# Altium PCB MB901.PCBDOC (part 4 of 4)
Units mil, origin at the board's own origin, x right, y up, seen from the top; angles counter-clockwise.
Board outline 4505 x 7005 mil, 4 copper layers (TopLayer, GND, VCC, BottomLayer); 333 components, 312 nets, 1570 pads, 794 vias.
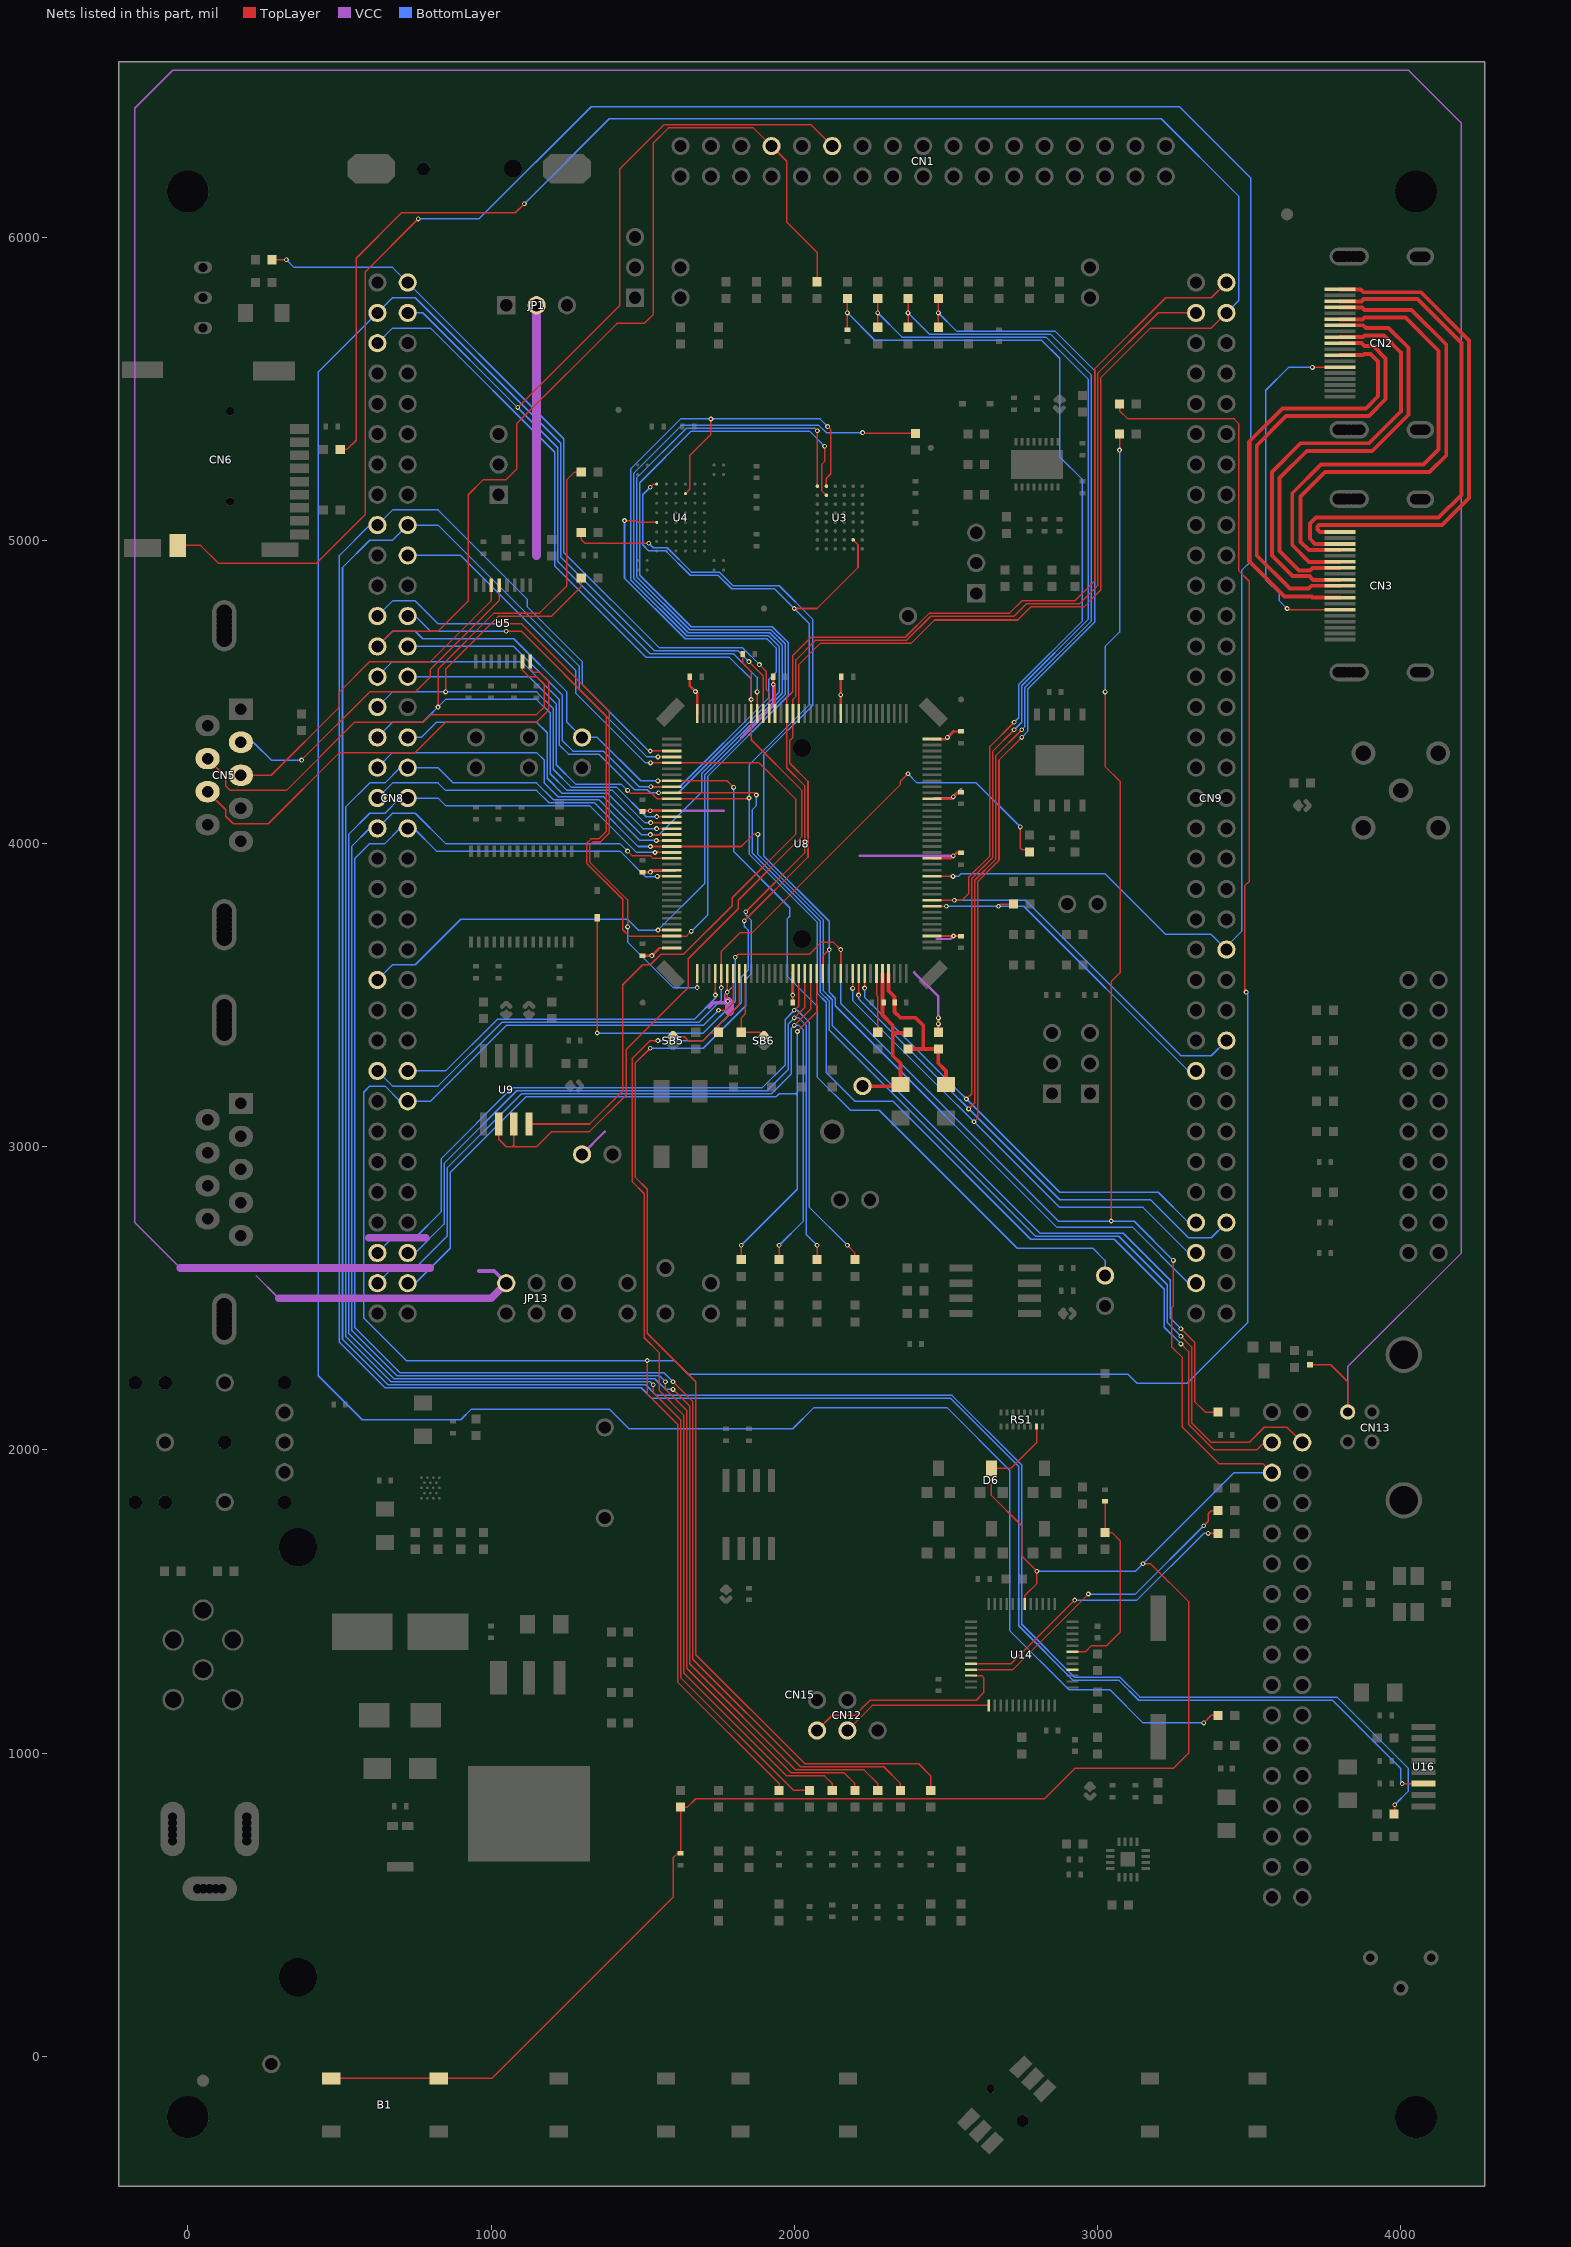
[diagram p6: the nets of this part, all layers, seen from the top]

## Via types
v1: diameter 16, hole 8, TopLayer to BottomLayer, tented both sides, 671 vias
v2: diameter 16, hole 8, TopLayer to BottomLayer, 117 vias
v3: diameter 50, hole 28, TopLayer to BottomLayer, 5 vias
v4: diameter 50, hole 28, TopLayer to BottomLayer, tented both sides, 1 vias

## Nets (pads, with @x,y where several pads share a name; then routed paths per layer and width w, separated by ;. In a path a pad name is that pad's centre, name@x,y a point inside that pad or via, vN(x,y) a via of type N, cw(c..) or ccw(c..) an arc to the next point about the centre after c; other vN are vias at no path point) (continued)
PC1: C10.2 CN9.65 R6.1 U8.27 | length 4896.7
  TopLayer w5: v1(2192.32,3522.32) U8.27@2192.32,3570.87 ; C10.2@2475,5702.5 R6.1@2475,5797.5 ; v1(2592.63,3082.37) 2605,3094.74 2605,3875 2675,3945 2675,4275 v1(2750,4350)
  BottomLayer w5: v1(2192.32,3522.32) 2192.32,3482.68 2875,2800 3150,2800 3300,2650 CN9.65@3325,2650 ; v1(2475,5750) 2535,5690 2860,5690 2990,5560 2990,4730 2770.59,4510.59 2770.59,4370.59 v1(2750,4350)
PC2: C9.2 CN9.64 R5.1 U8.28 | length 5015.9
  TopLayer w5: v1(2212.01,3500) U8.28@2212.01,3570.87 ; C9.2@2375,5702.5 R5.1@2375,5797.5 ; v1(2575,3125) 2595,3145 2595,3879.14 2665,3949.14 2665,4290 v1(2750,4375)
  BottomLayer w5: v1(2212.01,3500) 2212.01,3487.99 2875,2825 3175,2825 3300,2700 3375,2700 CN9.64@3425,2750 ; v1(2375,5750) 2445,5680 2845,5680 2980,5545 2980,4734.14 2760,4514.14 2760,4430 ; v1(2750,4375) 2760.59,4385.59 2760.59,4430
PC3: C8.2 CN9.63 R4.1 U8.29 | length 4899.1
  TopLayer w5: v1(2231.69,3523.31) U8.29@2231.69,3570.87 ; C8.2@2275,5702.5 R4.1@2275,5797.5 ; v1(2567.58,3157.42) 2585,3174.84 2585,3885 2655,3955 2655,4305 v1(2725,4375)
  BottomLayer w5: v1(2231.69,3523.31) 2231.69,3493.31 2875,2850 3200,2850 3300,2750 CN9.63@3325,2750 ; v1(2275,5750) 2355,5670 2830,5670 2970,5530 2970,4740 2750,4520 2750,4400 v1(2725,4375)
PC4: CN9.53 R47.1 U8.44 | length 1147.9
  TopLayer w5: U8.44@2454.13,3793.31 v1(2501.69,3793.31) ; v1(2673.31,3793.31) 2680,3800 R47.1@2722.5,3800
  BottomLayer w5: v1(2501.69,3793.31) 2756.69,3793.31 3300,3250 CN9.53@3325,3250
PC5: C7.2 CN9.52 R3.2 U8.45 | length 4076.7
  TopLayer w5: C7.2@2175,5694.5 R3.2@2175,5797.5 ; U8.45@2454.13,3812.99 2552.99,3812.99 2575,3835 2575,3889.14 2645,3959.14 2645,4320 v1(2725,4400)
  BottomLayer w5: v1(2175,5750) 2265,5660 2815,5660 2875,5600 2875,5275 2950,5200 2950,4734.14 2740,4524.14 2740,4415 v1(2725,4400) ; v1(2527.99,3812.99) 2762.01,3812.99 3275,3300 3375,3300 CN9.52@3425,3350
PC6: CN8.2 R1.1 U8.96 | length 2554.2
  TopLayer w5: R1.1@277.5,5925 v2(325,5925) ; v1(1885,4590) 1907.05,4567.95 1907.05,4507.95 1916.73,4498.27 U8.96@1916.73,4429.13
  BottomLayer w5: v2(325,5925) 350,5900 675,5900 1240,5335 1240,4960 1555,4645 1830,4645 v1(1885,4590)
PC7: CN8.3 R95.1 U8.97 | length 9587.2
  TopLayer w5: v1(1850,4600) 1897.05,4552.95 U8.97@1897.05,4429.13 ; v2(3350,1100) 3375,1125 R95.1@3397.5,1125
  BottomLayer w5: v1(1850,4600) 1815,4635 1540,4635 1230,4945 1230,5320 750,5800 675,5800 430,5555 430,2245 575,2100 900,2100 935,2135 1390,2135 1455,2070 1995,2070 2065,2140 2503.43,2140 2710,1933.43 2710,1405 2905,1210 3040,1210 3150,1100 v2(3350,1100)
PC8: CN1.23 CN8.4 U8.98 | length 3703.3
  TopLayer w5: v2(1088.08,5438.08) 1425,5775 1425,6225 1570,6370 2055,6370 CN1.23@2125,6300 ; U8.98@1877.36,4429.13 v1(1877.36,4500)
  BottomLayer w5: CN8.4@725,5750 775,5750 v2@1087.5,5437.5 ; v2@1088.08,5436.92 1220,5305 1220,4930 1525,4625 1800,4625 1877.36,4547.64 v1(1877.36,4500)
PC9: CN8.5 R40.2 U8.99 U9.2 U9.3 | length 4435.7
  TopLayer w5: U9.2@1025,3075 1025,3025 1050,3000 1150,3000 1200,3050 1325,3050 1445,3170 1445,3320 1650,3525 1650,3620 1815,3785 1815,3812.57 2025.11,4022.68 2025.11,4174.89 1857.68,4342.32 1857.68,4567.32 1830.5,4594.5 R40.2@1830.5,4625 ; 1070,3000 1075,3005 1080,3000 ; 1075,3000 U9.3@1075,3075
  BottomLayer w5: CN8.5@625,5650 675,5700 800,5700 1210,5290 1210,4915 1510,4615 1785,4615 1857.68,4542.32 v1(1857.68,4475)
PC10: CN8.17 U8.111 U16.3 | length 8663.8
  TopLayer w5: v1(1525,4305) 1525.12,4305.12 U8.111@1595.87,4305.12 ; v2(4004.8,899.8) U16.3@4075,899.8 4074.8,900 U16.3@4085,900
  BottomLayer w5: v1(1525,4305) 1520,4305 1300,4525 1300,4600 1120,4780 1120,4805 825,5100 675,5100 CN8.17@625,5050 600,5050 500,4950 500,2355 650,2205 1495,2205 1530,2170 2515.86,2170 2740,1945.86 2740,1420 2920,1240 3070.86,1240 3135.86,1175 3775,1175 4000,950 4000,904.61 v2(4004.8,899.8)
PC11: CN8.18 R110.2 U8.112 | length 8624.3
  TopLayer w5: v1(1550.43,4285.43) U8.112@1595.87,4285.43 ; R110.2@3980,802.5 v2(3980,830)
  BottomLayer w5: v1(1550.43,4285.43) 1514.57,4285.43 1290,4510 1290,4585 825,5050 CN8.18@725,5050 675,5000 600,5000 510,4910 510,2365 660,2215 1510,2215 1545,2180 2520,2180 2750,1950 2750,1425 2925,1250 3075,1250 3140,1185 3790,1185 4025,950 4025,875 v2(3980,830)
PC12: CN8.20 U8.113 U9.4 | length 3267.7
  TopLayer w5: U9.4@1125,3075 1325,3075 1434.08,3184.08 1434.08,3534.08 1500,3600 1525,3600 1560,3635 1635,3635 1795,3795 1795,3820.86 2005.11,4030.96 2005.11,4144.89 1884.25,4265.75 v1(1525.75,4265.75)
  BottomLayer w5: CN8.20@725,4950 900,4950 1280,4570 1280,4495 1509.25,4265.75 v1(1525.75,4265.75)
PC13: CN8.56 R11.1 R103.2 U8.7 | length 10330.9
  TopLayer w5: v2(1515,2295) 1515,2185 1615,2085 1615,1235 1950,900 R103.2@1950,877.5 ; v1(1750,3450) 1775,3450 1798.62,3473.62 U8.7@1798.62,3570.87 ; R11.1@3072.5,5450 3072.5,5427.5 3100,5400 3450,5400 3465,5385 3465,4900 3500,4865 3500,3875 3485,3860 3485,3515 v1(3490,3510)
  BottomLayer w5: v1(1750,3450) 1700,3400 1050,3400 800,3150 700,3150 650,3200 600,3200 580,3180 580,2435 720,2295 1605,2295 1650,2250 3100,2250 3130,2220 3295,2220 3495,2420 3495,3505 v1(3490,3510)
PC14: R59.2 SB5.2 U8.8 | length 388.4
  TopLayer w5: SB5.2@1600,3363 1637,3363 1650,3350 1700,3350 1725,3375 1747.5,3375 R59.2@1750,3377.5 1750,3400 1818.31,3468.31 U8.8@1818.31,3570.87
PC15: R60.2 SB6.2 U8.9 | length 279.8
  TopLayer w5: U8.9@1837.99,3570.87 1837.99,3437.99 1825,3425 R60.2@1825,3377.5 1885.5,3377.5 SB6.2@1900,3363
PD2: C1.2 CN1.27 CN8.25 JP9.2 JP12.1 U8.116 | length 6961.1
  TopLayer w5: CN8.25@625,4650 675,4700 825,4700 925,4800 925,5150 975,5200 1050,5200 1085,5235 1085,5385 1415,5715 1505,5715 1535,5745 1535,6310 1585,6360 1865,6360 1975,6250 1975,6050 2075,5950 C1.2@2075,5852.5 ; v1(1550,4206.69) 1778.31,4206.69 v1(1800,4185)
  BottomLayer w5: CN8.25@625,4650 675,4700 750,4700 775,4675 1075,4675 1250,4500 1250,4400 JP9.2@1300,4350 1350,4350 1493.31,4206.69 v1(1550,4206.69) ; v1(1800,4185) 1800,3973.43 1985,3788.43 1985,3760 1976.1,3751.1 1976.1,3563.04 2075,3464.14 2075,3230 2185,3120 2280,3120 2735,2665 2985,2665 3025,2625 JP12.1@3025,2575
PD3: CN8.26 U4.E1 U8.117 | length 2729.1
  TopLayer w5: v1(1440,5065) 1479.25,5065 1485,5059.25 U4.E1@1546.26,5059.25 ; v1(1527.01,4187.01) U8.117@1595.87,4187.01
  BottomLayer w5: CN8.26@725,4650 1075,4650 1235,4490 1235,4340 1270,4305 1370,4305 1487.99,4187.01 1622.01,4187.01 1915,4480 1915,4540 1940,4565 1940,4645 1910,4675 1640,4675 1440,4875 v1(1440,5065)
PD4: CN8.27 CN15.4 U3.A2 U4.B4 U8.118 | length 7659.8
  TopLayer w5: v1(1552.32,4167.32) 1867.68,4167.32 v2(1875,4160) ; U4.B4@1640.75,5153.74 1655,5167.99 1655,5280 1725,5350 v1(1725,5400) ; U3.A2@2105.71,5178.35 2105.71,5204.85 2120,5219.14 2120,5365 v1(2110,5375) ; v1(3275,2375) 3310,2340 3310,2090 3375,2025 3500,2025 3550,2075 3625,2075 CN15.4@3675,2025
  BottomLayer w5: CN8.27@625,4550 675,4600 1100,4600 1225,4475 1225,4325 1255,4295 1355,4295 1472.99,4177.01 1515,4177.01 1524.68,4167.32 1617.32,4167.32 1950,4500 1950,4650.15 1915.15,4685 1645,4685 1460,4870 1460,5235 1625,5400 2085,5400 v1(2110,5375) ; v2(1875,4160) 1875,4125 1860.67,4110.67 1860.67,3969.33 2085,3745 2085,3510.71 2115,3480.71 2115,3385 2795,2705 3070,2705 3230,2545 3230,2420 v1(3275,2375)
PD5: CN8.28 CN15.3 U3.G5 U4.A1 U8.119 | length 6535.7
  TopLayer w5: v1(1450,4175) 1460,4165 1530,4165 1547.36,4147.64 v1@1847.64,4147.64 ; v1(1525,5175) 1535.24,5185.24 U4.A1@1546.26,5185.24 ; v1(2000,4775) 2075,4775 2210,4910 2210,4985.47 U3.G5@2194.29,5001.18 ; v1(3275,2350) 3300,2325 3300,2085 3385,2000 3525,2000 3550,2025 CN15.3@3575,2025
  BottomLayer w5: CN8.28@725,4550 1125,4550 1215,4460 1215,4260 1280,4195 1430,4195 v1(1450,4175) ; v1(1525,5175) 1500,5150 1500,4985 1520,4965 1576.72,4965 1656.72,4885 1748.43,4885 1793.43,4840 1935,4840 2050,4725 2050,4458.58 1850.67,4259.25 1850.67,3965.19 2075,3740.86 2075,3506.57 2105,3476.57 2105,3245 2200,3150 2325,3150 2780,2695 3055,2695 3220,2530 3220,2405 v1(3275,2350) ; v1@1847.64,4147.64 v1@1850.67,4150.67
  other v1: 1850.67,4150
PD6: CN8.29 R36.2 U8.122 | length 1942
  TopLayer w5: v1(850,4500) 850,4575 1025,4750 1200,4750 1297.5,4847.5 R36.2@1297.5,4875 ; v1(1546.42,4088.58) U8.122@1595.87,4088.58
  BottomLayer w5: CN8.29@625,4450 675,4500 1150,4500 1205,4445 1205,4245 1265,4185 1415,4185 1511.42,4088.58 v1(1546.42,4088.58)
PD7: CN8.31 R22.2 U8.123 | length 2379.8
  TopLayer w5: v1(825,4450) 825,4575 1010,4760 1160,4760 1250,4850 1250,5200 1275,5225 R22.2@1297.5,5225 ; v1(1526.1,4068.9) U8.123@1595.87,4068.9
  BottomLayer w5: CN8.31@625,4350 675,4400 775,4400 850,4475 1150,4475 1195,4430 1195,4230 1250,4175 1400,4175 1506.1,4068.9 v1(1526.1,4068.9)
PE0: CN8.47 U3.A1 U8.141 | length 3944.4
  TopLayer w5: v1(1550.43,3714.57) U8.141@1595.87,3714.57 ; U3.A1@2076.18,5178.35 v1(2076.18,5361.18)
  BottomLayer w5: CN8.47@625,3550 675,3600 750,3600 900,3750 1450,3750 1485.43,3714.57 v1(1550.43,3714.57) ; v1@1550,3715 v1(1550.43,3714.57) ; v1(2076.18,5361.18) 2067.36,5370 1645,5370 1480,5205 1480,4880 1655,4705 1923.43,4705 1970,4658.43 1970,4491.72 1705,4226.72 1705,3869.14 v1(1550.43,3714.57)
PE1: CN8.24 U3.B2 U8.142 | length 4673.3
  TopLayer w5: v1(1050,4700) 1100,4700 1380,4420 1380,4040 1355,4015 1329.14,4015 1315,4000.86 1315,3935 1434.08,3815.92 1434.08,3715.92 1455.12,3694.88 1644.88,3694.88 v1(1660,3710) ; v1(2100,5310) 2100,5260 2090,5250 2090,5164.53 U3.B2@2105.71,5148.82
  BottomLayer w5: CN8.24@725,4750 750,4750 800,4700 v1(1050,4700) ; v1(1660,3710) 1715,3765 1715,4222.57 1980,4487.57 1980,4662.57 1927.57,4715 1660,4715 1490,4885 1490,5190 1660,5360 2050,5360 v1(2100,5310)
PE2: CN8.23 U8.1 | length 2127.7
  TopLayer w5: v1(1025,4725) 1100,4725 1390,4435 1390,4035 1360,4005 1335,4005 1325,3995 1325,3939.14 1450,3814.14 v1(1450,3725) ; v1@1680.51,3525.51 U8.1@1680.51,3570.87
  BottomLayer w5: CN8.23@625,4750 675,4800 750,4800 825,4725 v1(1025,4725) ; v1(1450,3725) 1450,3675 1600,3525 v1(1680,3525)
PE5: CN8.54 U8.4 | length 1195.1
  TopLayer w5: v1(1739.57,3500.43) U8.4@1739.57,3570.87
  BottomLayer w5: CN8.54@725,3250 850,3250 1020,3420 1670,3420 1739.57,3489.57 v1(1739.57,3500.43)
PE6: CN8.53 R44.2 U8.5 | length 2841.5
  TopLayer w5: v1(1759.25,3525) 1759.25,3644.25 1820,3705 1860,3705 2350,4195 2350,4205 v2(2375,4230) ; v2(2745,4055) 2745,3985 2750,3980 R44.2@2775,3980
  BottomLayer w5: CN8.53@625,3250 675,3200 825,3200 1035,3410 1685,3410 1759.25,3484.25 v1(1759.25,3525) ; v2(2375,4230) 2405,4200 2600,4200 v2(2745,4055)
PF6: CN8.65 R76.2 U8.18 | length 2935.1
  TopLayer w5: v1(2000,3450) 2015.16,3465.16 U8.18@2015.16,3570.87 ; v1(2175,2675) 2200,2650 R76.2@2200,2627.5
  BottomLayer w5: CN8.65@625,2650 675,2700 750,2700 835,2785 835,2960 1070,3195 1895,3195 1970,3270 1970,3420 v1(2000,3450) 2010,3450 2050,3410 2050,2800 v1(2175,2675)
PF7: CN8.66 R75.2 U8.19 | length 2798.7
  TopLayer w5: v1(2000,3425) 2034.84,3459.84 U8.19@2034.84,3570.87 ; R75.2@2075,2627.5 v1(2075,2675)
  BottomLayer w5: CN8.66@725,2650 750,2650 845,2745 845,2945 1085,3185 1910,3185 1980,3255 1980,3405 v1(2000,3425) 2015,3425 2040,3400 2040,2710 v1(2075,2675)
PF8: CN8.67 R74.2 U8.20 | length 2967.1
  TopLayer w5: R74.2@1950,2627.5 v1(1950,2675) ; v1(2000,3400) 2054.53,3454.53 U8.20@2054.53,3570.87
  BottomLayer w5: CN8.67@625,2550 675,2600 750,2600 855,2705 855,2930 1100,3175 1925,3175 1990,3240 1990,3390 v1(2000,3400) 2015,3400 2030,3385 2030,2755 v1(1950,2675)
PF9: CN8.68 R73.2 U8.21 | length 2751.1
  TopLayer w5: R73.2@1825,2627.5 v1(1825,2675) ; v1(2010,3380) 2074.21,3444.21 U8.21@2074.21,3570.87
  BottomLayer w5: CN8.68@725,2550 750,2550 865,2665 865,2915 1115,3165 1940,3165 1950,3175 2010,3175 ; v1(1825,2675) 2010,2860 v1(2010,3380) ; 2010,3170 2005,3175 2010,3180
PF10: CN9.67 R28.1 U8.22 | length 3990.3
  TopLayer w5: R28.1@1297.5,5025 1297.5,5002.5 1310,4990 v1(1520,4990) ; U8.22@2093.9,3570.87 2093.9,3628.9 v2(2115,3650)
  BottomLayer w5: v1(1520,4990) 1535,4975 1580.86,4975 1660.86,4895 1752.57,4895 1797.57,4850 1950,4850 2060,4740 2060,4454.44 1898.72,4293.16 1898.72,3959.56 2115,3743.28 2115,3510 2135,3490 2135,3465 2865,2735 3115,2735 3300,2550 CN9.67@3325,2550
PF11: CN6.10 CN9.46 U8.49 | length 8397.6
  TopLayer w5: CN6.10@-33.23,4983.07 41.93,4983.07 100,4925 425,4925 585,5085 585,5885 v2(760,6060) ; U8.49@2454.13,3891.73 v1(2523.27,3891.73)
  BottomLayer w5: v2(760,6060) 960,6060 1330,6430 3270,6430 3505,6195 3505,4930 3475,4900 3475,3710 CN9.46@3425,3660 ; v1(2523.27,3891.73) 2541.73,3891.73 2550,3900 3025,3900 3225,3700 3375,3700 CN9.46@3425,3650
PG6: CN9.4 R16.1 U8.91 | length 6734
  TopLayer w5: R16.1@502.5,5300 525,5300 555,5330 555,5930 705,6080 1080,6080 v2(1110,6110) ; U8.91@2015.16,4429.13 2015.16,4590.16 2085,4660 2385,4660 2462.07,4737.07 2737.07,4737.07 2780,4780 2955,4780 3010,4835 3010,5535 3175,5700 3375,5700 CN9.4@3425,5750
  BottomLayer w5: v2(1110,6110) 1390,6390 3210,6390 3465,6135 3465,5790 CN9.4@3425,5750
PG7: CN9.3 R105.2 U8.92 | length 6664.7
  TopLayer w5: v1(1550,3350) 1525,3350 1465,3290 1465,2885 1505,2845 1505,2370 1555,2320 1555,2195 1635,2115 1635,1265 1975,925 2100,925 2125,900 R105.2@2125,877.5 ; v1(1835,3745) 2045.11,3955.11 2045.11,4204.89 1985,4265 1985,4340 1995.47,4350.47 1995.47,4475 2005.16,4484.69 2005.16,4605.16 2070,4670 2370,4670 2449.62,4749.62 2724.62,4749.62 2765,4790 2940,4790 3000,4850 3000,5550 3200,5750 CN9.3@3325,5750
  BottomLayer w5: v1(1550,3350) 1700,3350 1825,3475 1825,3560 1847.36,3582.36 1847.36,3715 1835,3727.36 v1(1835,3745)
PG8: CN9.2 R109.2 U8.93 | length 7097.6
  TopLayer w5: v1(1525,3325) 1475,3275 1475,2900 1515,2860 1515,2385 1675,2225 1675,1325 2035,965 2410,965 2450,925 R109.2@2450,877.5 ; v1(1840,3775) 2035.11,3970.11 2035.11,4189.89 1975,4250 1975,4480 1995.16,4500.16 1995.16,4620.16 2055,4680 2365.86,4680 2445.86,4760 2710,4760 2750,4800 2925,4800 2990,4865 2990,5565 3225,5800 3375,5800 CN9.2@3425,5850
  BottomLayer w5: v1(1525,3325) 1700,3325 1840,3465 1840,3552.32 1857.36,3569.68 1857.36,3747.64 1840,3765 v1(1840,3775)
PG9: CN8.32 U8.124 | length 1124.7
  TopLayer w5: v1(1545.79,4049.21) U8.124@1595.87,4049.21
  BottomLayer w5: CN8.32@725,4350 770,4350 820,4400 1150,4400 1185,4365 1185,4215 1235,4165 1385,4165 1500.79,4049.21 v1(1545.79,4049.21)
PG10: CN8.33 R18.2 U8.125 | length 3903.4
  TopLayer w5: v1(1525.47,4029.53) U8.125@1595.87,4029.53 ; v1(2225,5355) 2227.5,5352.5 R18.2@2400,5352.5
  BottomLayer w5: CN8.33@625,4250 675,4300 1150,4300 1175,4275 1175,4200 1220,4155 1370,4155 1495.47,4029.53 1554.53,4029.53 1695,4170 1695,4230.86 1960,4495.86 1960,4654.29 1919.29,4695 1650,4695 1470,4875 1470,5220 1630,5380 2080,5380 2105,5355 v1(2225,5355)
PG11: CN8.34 R104.2 U8.126 | length 5637
  TopLayer w5: v2(1535,2215) 1535,2190 1625,2100 1625,1250 1997.5,877.5 R104.2@2050,877.5 ; v1(1545.16,4009.84) U8.126@1595.87,4009.84
  BottomLayer w5: v2(1535,2215) 1525,2225 670,2225 520,2375 520,4120 600,4200 650,4200 700,4250 825,4250 875,4200 1150,4200 1205,4145 1355,4145 1490,4010 1545,4010 v1(1545.16,4009.84)
PG12: CN8.35 R85.2 U8.127 | length 4098.7
  TopLayer w5: v1(1525.16,3990.16) 1825.16,3990.16 1865,4030 v2(1880,4030) ; v1(3275,2400) 3320,2355 3320,2160 3355,2125 R85.2@3397.5,2125
  BottomLayer w5: CN8.35@625,4150 675,4200 825,4200 850,4175 1150,4175 1190,4135 1340,4135 1484.84,3990.16 v1(1525.16,3990.16) ; v2(1880,4030) 1880,3964.14 2095,3749.14 2095,3514.85 2125,3484.85 2125,3400 2810,2715 3085,2715 3240,2560 3240,2435 v1(3275,2400)
PG13: CN8.36 R107.2 U8.128 | length 5715.5
  TopLayer w5: v1(1540.47,3970.47) U8.128@1595.87,3970.47 ; v2(1600,2200) 1655,2145 1655,1295 2005,945 2230,945 2275,900 R107.2@2275,877.5
  BottomLayer w5: v1(1540.47,3970.47) 1479.53,3970.47 1325,4125 850,4125 825,4150 700,4150 650,4100 600,4100 530,4030 530,2385 680,2235 1540,2235 1575,2200 v2(1600,2200)
PG14: CN8.37 R106.2 U8.129 | length 5572.5
  TopLayer w5: v1(1450,3975) 1465,3960 1525,3960 1534.21,3950.79 U8.129@1595.87,3950.79 ; v2(1575,2225) 1575,2200 1645,2130 1645,1280 1990,935 2165,935 2200,900 R106.2@2200,877.5
  BottomLayer w5: v1(1450,3975) 1425,4000 850,4000 750,4100 675,4100 CN8.37@625,4050 600,4050 540,3990 540,2395 690,2245 1555,2245 v2(1575,2225)
PG15: CN8.38 R108.2 U8.132 | length 5643.1
  TopLayer w5: v1(1548.27,3891.73) U8.132@1595.87,3891.73 ; v2(1600,2225) 1665,2160 1665,1310 2020,955 2295,955 2350,900 R108.2@2350,877.5
  BottomLayer w5: v1(1548.27,3891.73) 1541.73,3891.73 1540,3890 1510,3890 1425,3975 820,3975 745,4050 700,4050 650,4000 600,4000 550,3950 550,2405 700,2255 1570,2255 v2(1600,2225)
RESERVED: CN2.14 CN3.14 | length 1202.1
  TopLayer w5: v1(3625,4775) 3628.74,4771.26 CN3.14@3800,4771.26 ; v1(3708.74,5570) 3710,5571.26 CN2.14@3800,5571.26
  BottomLayer w5: v1(3625,4775) 3600,4800 3600,4825 3555,4870 3555,5495 3630,5570 v1(3708.74,5570)
RESET#: B1.2 B1.3 C84.2 CN15.5 D3.1 D6.3 R20.2 R111.1 RS1.13 U8.25 U14.18 | length 12496.5
  TopLayer w5: B1.2@472.83,-72.5 1002.5,-72.5 1600,525 1600,655 1614.5,669.5 C84.2@1625,669.5 R111.1@1625,822.5 1647.5,822.5 1675,850 2825,850 2925,950 3250,950 3300,1000 3300,1500 3175,1625 v2(3150,1625) ; v1(1350,3375) D3.1@1350,3755 ; v2(1805,3625) 1815,3635 2050,3635 2090,3675 2127.95,3675 v2(2152.95,3650) U8.25@2152.95,3570.87 ; U8.25@2155,3565 U8.25@2155,3570.87 ; U14.18@2759.84,1492.32 2759.84,1519.84 2800,1560 v2(2800,1600) 2750,1650 2750,1750 2650,1850 2650,1939.5 D6.3@2650.5,1940 2715,1940 2799.21,2024.21 RS1.13@2799.21,2077 ; v1(3025,4500) 3025,4254.29 3075,4204.29 3075,3575 3045,3545 v1(3045,2755) ; v1(3072.5,5297.5) R20.2@3072.5,5350 ; v1(3250,2625) 3250,2475 3245,2470 3245,2340 3280,2305 3280,2075 3400,1955 3545,1955 CN15.5@3575,1925
  BottomLayer w5: v1(1350,3375) 1700,3375 1805,3480 v2(1805,3625) ; v2(2152.95,3650) 2152.95,3472.05 2870.82,2754.18 3120.82,2754.18 v1(3250,2625) ; v2(2800,1600) 3125,1600 3450,1925 CN15.5@3575,1925 ; v1(3025,4500) 3025,4650 3072.5,4697.5 v1(3072.5,5297.5)
RS232_CTS2: CN5.8 U5.8 | length 1533.5
  TopLayer w5: CN5.8@65,4171 125,4111 125,4090 150,4065 265,4065 500,4300 750,4300 850,4400 1150,4400 1190,4440 1190,4535 1160,4565 1140,4565 1129.13,4575.87 U5.8@1129.13,4600
RS232_RTS2: CN5.7 U5.7 | length 1479.2
  TopLayer w5: CN5.7@65,4280 125,4220 125,4190 140,4175 325,4175 550,4400 775,4400 800,4425 1150,4425 1175,4450 1175,4525 1150,4550 1125,4550 1103.54,4571.46 U5.7@1103.54,4600
RS232_RX2: CN5.2 U5.13 | length 1159.2
  TopLayer w5: v2(375,4275) 600,4500 750,4500 800,4550 800,4575 1026.77,4801.77 U5.13@1026.77,4851.97
  BottomLayer w5: CN5.2@175,4334 216,4334 275,4275 v2(375,4275)
RS232_TX2: CN5.3 U5.14 | length 1144.9
  TopLayer w5: CN5.3@175,4225 275,4225 500,4450 500,4500 600,4600 800,4600 1001.18,4801.18 U5.14@1001.18,4851.97
STM_JTCK_SWCLK: CN12.3 U14.37 | length 501
  TopLayer w5: CN12.3@2175,1075 2257.68,1157.68 U14.37@2641.73,1157.68
STM_JTMS_SWDIO: CN12.1 U14.34 | length 696.6
  TopLayer w5: CN12.1@2075,1075 2125,1125 2200,1125 2250,1175 2600,1175 2625,1200 2625,1250 2618.9,1256.1 U14.34@2582.68,1256.1
STM_RST: C73.2 R87.1 U14.7 | length 649.1
  TopLayer w5: U14.7@2917.32,1334.84 2959.84,1334.84 2980,1355 3030,1355 3075,1400 3075,1700 3047.5,1727.5 R87.1@3025,1727.5 C73.2@3025,1830.5
SWIM_PU_CTRL: U14.4
TMDS_CLK+: CN2.10 CN3.10 | length 1480.5
  TopLayer w13: CN3.10@3800,4850 3705,4850 3696,4841 3634,4841 3525,4950 3525,5313 3622,5410 3895,5410 3950,5465 3950,5600 3910,5640 3880,5640 3870,5650 CN2.10@3800,5650
TMDS_CLK-: CN2.12 CN3.12 | length 1483
  TopLayer w13: CN3.12@3800,4810.63 3709.37,4810.63 3705,4815 3616.26,4815 3599.97,4831.29 3500,4931.26 3500,5325 3610,5435 3885,5435 3925,5475 3925,5590 3900,5615 3880,5615 3875.63,5610.63 CN2.12@3800,5610.63
TMDS_D0+: CN2.7 CN3.7 | length 1458.9
  TopLayer w13: CN3.7@3800,4909.06 3709.06,4909.06 3700,4900 3665,4900 3600,4965 3600,5205 3690,5295 3906,5295 4025,5414 4025,5635 3960,5700 3885,5700 3875.94,5709.06 CN2.7@3800,5709.06
TMDS_D0-: CN2.9 CN3.9 | length 1460.9
  TopLayer w13: CN3.9@3800,4869.68 3710.32,4869.68 3698.46,4881.54 3643.46,4881.54 3575,4950 3575,5225 3670,5320 3895,5320 4000,5425 4000,5619.69 3944.69,5675 3880,5675 3874.69,5669.69 CN2.9@3800,5669.69
TMDS_D1+: CN2.4 CN3.4 | length 1593.1
  TopLayer w13: CN3.4@3800,4968.11 3696.89,4968.11 3670,4995 3670,5145 3750,5225 4095,5225 4150,5280 4150,5645 4035,5760 3880,5760 3871.89,5768.11 CN2.4@3800,5768.11
TMDS_D1-: CN2.6 CN3.6 | length 1592.9
  TopLayer w13: CN3.6@3800,4928.74 3697.62,4928.74 3642,4984.36 3642,5155 3737,5250 4075,5250 4125,5300 4125,5625 4015,5735 3880,5735 3873.74,5728.74 CN2.6@3800,5728.74
TMDS_D2+: CN2.1 CN3.1 | length 1641.8
  TopLayer w13: CN3.1@3800,5027.17 3732.83,5027.17 3725,5035 3725,5045 3730,5050 4136,5050 4225,5139 4225,5659 4066,5818 3877,5818 3867.83,5827.17 CN2.1@3800,5827.17
TMDS_D2-: CN2.3 CN3.3 | length 1659.5
  TopLayer w13: CN3.3@3800,4987.8 3717.2,4987.8 3700,5005 3700,5055 3720,5075 4125,5075 4200,5150 4200,5650 4055,5795 3877.2,5795 3870,5787.8 CN2.3@3800,5787.8
U5V_ST_LINK: CN13.1 JP13.2 R130.1 | length 15036.7
  TopLayer w5: R130.1@3700,2281 3769,2281 3825,2225 CN13.1@3825,2125
  VCC w5: -25,2600 -175,2750 -175,6425 -50,6550 4025,6550 4200,6375 4200,2650 3825,2275 CN13.1@3825,2125 ; 225,2575 300,2500
  VCC w12: 960,2590 1010,2590 JP13.2@1050,2550
  VCC w25: -25,2600 800,2600 ; 300,2500 1000,2500 JP13.2@1050,2550 ; 596.61,2700 785,2700
USB_DM: R133.1 U14.32 | length 992.7
  TopLayer w5: U14.32@2582.68,1295.47 2715.47,1295.47 v2(2925,1505) ; v2(3365,1725) R133.1@3397.5,1725
  BottomLayer w5: v2(2925,1505) 3130,1505 3350,1725 v2(3365,1725)
USB_DP: R134.1 U14.33 | length 1046.6
  TopLayer w5: U14.33@2582.68,1275.79 2720.79,1275.79 v2(2970,1525) ; v2(3350,1750) 3365,1765 3365,1790 3375,1800 R134.1@3397.5,1800
  BottomLayer w5: v2(2970,1525) 3125,1525 v2(3350,1750)
VBAT: JP1.2 U8.6 | length 1070
  TopLayer w5: U8.6@1778.94,3570.87 1778.94,3491.06 1778.94,3481.06 v1(1780,3480)
  VCC w5: 1770,3487.67 1770,3501.06 1793.94,3525
  VCC w12: 1718.55,3460 1733.55,3475 v1@1785,3475
  VCC w30: 1150,4950 JP1.2@1150,5775 ; v1@1781.72,3478.28 1786.42,3473.58 1786.42,3446.42
  other v1: 1778.94,3510
VDD: C28.1 C29.1 C30.1 C32.1 C35.1 C36.1 C38.1 C39.1 C43.1 C44.1 C48.1 JP10.1 L1.2 U8.17 U8.39 U8.52 U8.62 U8.72 U8.84 U8.95 U8.108 U8.121 U8.131 U8.144 | length 2621.7
  TopLayer w8: C43.1@1500,3630.5 v1(1530.5,3630.5) 1555.51,3655.51 U8.144@1595.87,3655.51 ; C38.1@1500,3905.5 v1(1525.5,3905.5) 1531.42,3911.42 U8.131@1595.87,3911.42 ; C35.1@1502.77,4108.27 U8.121@1595.87,4108.27 ; C28.1@1655.5,4550 1655.5,4519.5 1680.51,4494.49 U8.108@1680.51,4429.13 ; C29.1@1930.5,4550 v1(1930.5,4524.5) 1936.42,4518.58 U8.95@1936.42,4429.13 ; C48.1@1995.47,3475.97 U8.17@1995.47,3570.87 ; U8.84@2152.95,4429.13 C30.1@2152.95,4547.45 ; U8.39@2454.13,3694.88 C44.1@2549.62,3694.88 ; U8.52@2454.13,3950.79 2515.79,3950.79 2534.5,3969.5 C39.1@2550,3969.5 ; U8.62@2454.13,4147.64 2518.14,4147.64 2540,4169.5 C36.1@2550,4169.5 ; U8.72@2454.13,4344.49 2500,4344.49 2515.26,4359.74 2525.01,4369.5 C32.1@2550,4369.5 ; L1.2@2475,3377.5 v1(2475,3425)
  VCC w8: JP10.1@1300,2975 1375,3050 ; v1(1525,4108.27) 1766.73,4108.27 ; v1(1525.5,3905.5) 1530,3910 1605,3910 ; 1825.48,4349.52 1930.5,4454.54 v1(1930.5,4524.5) ; v1@1995.47,3500 1995.47,3574.53 ; 2215.67,3959.33 v1(2524.33,3959.33) ; 2395,3575 2475,3495 v1(2475,3425) ; 2465,4150 2520.5,4150 2550,4179.5 ; 2470,3685 2515.12,3685 v1(2525,3694.88) ; v1(2505,4350) 2525,4370
  other v1: 2475,3405 1995,3500 2524.3,4153.8 2152.95,4490 1673.6,4501.4
VDDA: C46.2 C54.1 L1.1 R62.2 U8.33 | length 553
  TopLayer w12: U8.33@2310.43,3570.87 2310.43,3514.57 2330.5,3494.5 2330.5,3444.5 2350,3425 2400,3425 2425,3400 2425,3322.5 ; R62.2@2375,3322.5 L1.1@2475,3322.5 2475,3275 2500,3250 C54.1@2500,3205
VREF+: C47.1 C55.1 R62.1 TP3.1 U8.32 | length 572.9
  TopLayer w12: TP3.1@2225,3200 C55.1@2360,3200 ; U8.32@2290.75,3570.87 2290.75,3434.25 2325,3400 2325,3300 2350,3275 C55.1@2350,3205 ; 2325,3375 R62.1@2372.5,3375
VREF-: R61.1 U8.31 | length 195
  TopLayer w5: U8.31@2271.06,3570.87 2271.06,3500 2275,3496.06 R61.1@2275,3377.5
pads on no net: BT1.0 CN5.9 CN6.0 CN6.1 CN6.8 CN8.11 CN9.38 CN9.48 CN9.49 CN9.62 CN9.68 CN10.1 CN10.7 CN11.0 CN12.5 CN15.0 CN15.29 CN15.30 D4.1 D5.1 D6.1 D7.1 D8.1 D9.1 mp1.0 mp2.0 RS1.1 RS1.2 RS1.15 RS1.16 U2.2 U2.15 U3.E3 U4.J0 U6.0 U7.4 U7.8 U7.9 U7.11 U7.12 U7.14 U7.15 U7.18 U7.19 U7.21 U8.0 U8.106 U11.E7 U14.11 U14.12 U14.13 U14.14 U14.21 U14.22 U14.28 U14.38 U14.39 U14.40 U14.41 U14.42 U14.43 U14.45 U14.46 U16.2 U19.0 U19.8 U19.12 U20.0 X2.2 X2.3
copper on no net: | length 12020
  TopLayer w5: 2075,1525 2200,1525 ; 2075,1650 2200,1650 2325,1650 ; 2075,1775 2200,1775 2325,1775 ; 2180,1525 2325,1525 ; 2200,1275 2200,1400 ; 2200,2025 2200,1900 ; 2075,1400 2075,1275 2325,1275 2325,1400 ; 2075,1400 2200,1400 ; 2075,1400 2075,1900 ; 2075,1900 2075,2025 2320,2025 2325,2025 2325,1900 ; 2075,1900 2200,1900 ; 2200,1400 2200,1900 ; 2200,1400 2325,1400 ; 2200,1900 2325,1900 ; 2325,1400 2325,1900
  VCC w5: 2075,1400 2325,1400 ; 2075,1525 2325,1525 ; 2075,1650 2325,1650 ; 2075,1775 2325,1775 ; 2200,1275 2200,1900 2200,2025 ; 2075,1900 2075,2025 2325,2025 2325,1900 ; 2075,1900 2075,1275 2325,1275 2325,1900 ; 2075,1900 2325,1900
  BottomLayer w5: 2075,1525 2200,1525 2325,1525 ; 2075,1650 2200,1650 2325,1650 ; 2075,1775 2200,1775 2325,1775 ; 2200,1275 2200,1400 ; 2200,2025 2200,1900 ; 2075,1400 2075,1275 2325,1275 2325,1400 ; 2075,1400 2200,1400 ; 2075,1400 2075,1900 ; 2075,1900 2075,2025 2325,2025 2325,1900 ; 2075,1900 2200,1900 ; 2200,1400 2200,1900 ; 2200,1400 2325,1400 ; 2200,1900 2325,1900 ; 2325,1400 2325,1900

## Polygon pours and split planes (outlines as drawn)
GND on TopLayer (hatched 90Degree grid 20 track 10, remove dead copper): -230,6575 4270,6575 4270,-425 -225,-425 -225,6575
+3V3 on VCC (hatched 90Degree grid 15 track 15, remove dead copper): -215,2450 1125,2450 1125,2080 980,1935 650,1935 650,1315 975,990 1100,990 1100,1215 880,1435 880,1645 1005,1770 1420,1770 1420,730 1290,600 740,600 440,900 440,1260 240,1460 95,1460 95,525 1365,525 1500,660 1500,2155 1345,2310 1345,2590 1290,2590 1290,2700 725,3265 510,3480 255,3735 255,6395 3480,6395 3480,3745 4190,3745 4190,2565 3770,2565 3770,2100 4275,2100 4275,-420 -225,-420 -225,2455
U5V_ST_LINK on VCC (hatched 90Degree grid 15 track 15, remove dead copper): -225,2450 1100,2450 1100,2600 875,2825 175,2825 175,6475 3430,6475 3430,3725 4150,3725 4150,2575 3750,2575 3750,2075 4275,2075 4275,6575 -225,6575
VBAT on VCC (hatched 90Degree grid 10 track 10, remove dead copper): 1100,5825 1200,5825 1200,4950 1400,4750 1400,3600 1525,3475 1550,3450 1700,3450 1750,3500 1775,3525 1815,3525 1815,3400 1500,3400 1325,3575 1325,4700 1125,4900 1100,4925
E5V on VCC (hatched 90Degree grid 10 track 10, remove dead copper): 100,1425 100,1450 250,1450 425,1275 425,900 725,600 1300,600 1425,725 1425,2100 1275,2250 1275,2470 1225,2520 1225,2600 1355,2600 1355,2300 1500,2155 1500,675 1350,525 100,525
+5V on VCC (hatched 90Degree grid 10 track 10, remove dead copper): 975,1000 1100,1000 1100,1225 880,1445 880,1625 1025,1770 1429.73,1770 1429.73,2160 1290,2299.73 1290,2700 900,3090 900,3175 975,3250 975,3520 925,3570 925,5775 1400,6250 2025,6250 2045,6230 2045,6125 2070,6100 2900,6100 3000,6000 3000,5150 2975,5125 2850,5125 2850,5050 3025,5050 3100,5125 3100,6250 2225,6250 2075,6400 1400,6400 850,5850 850,2975 1185,2640 1185,2500 1125,2500 1125,2050 1000,1925 650,1925 650,1325
D5V on VCC (hatched 90Degree grid 10 track 10, remove dead copper): 1075,2475 1200,2475 1200,2670 890,2980 890,3475 525,3475 300,3700 300,6075 625,6400 3070,6400 3070,4875 3430,4875 3430,6475 175,6475 175,2816 825,2816 1085,2556 1085,2475
VDD on VCC (hatched 90Degree grid 10 track 10, remove dead copper): 1250,2925 1350,2925 1350,3000 1580,3230 2150,3230 2150,3525 2355,3525 2430,3450 2430,3375 2575,3375 2575,4600 1400,4600 1400,3605 1560,3445 1750,3445 1750,3400 1500,3400 1200,3100 1200,2925
GND on BottomLayer (hatched 90Degree grid 20 track 10, remove dead copper): -225,6575 4275,6575 4275,-425 -225,-425

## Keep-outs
KeepOutLayer:
  lines w4: 2075,1275 2075,1400 ; 2075,1525 2200,1525 2325,1525 ; 2075,1650 2200,1650 2325,1650 ; 2075,1775 2200,1775 2325,1775 ; 2200,1275 2200,1400 ; 2325,1275 2325,1400 ; 2075,1400 2200,1400 ; 2075,1400 2075,1900 2200,1900 ; 2200,1400 2325,1400 ; 2200,1400 2200,1900 ; 2200,1900 2325,1900 2325,1400
  lines w5: 2075,1275 2325,1275 ; -225,-425 -225,5025 ccw(c-1380.29,5270.56) -225,5516.13 -225,6575 4275,6575 4275,-425 -225,-425

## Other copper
TopLayer:
  text "1" at 2175,1450 h50 r90
  text "B" at 2285,1440 h50 r90
VCC:
  text "3" at 2175,1735 h50 r90
  text "B" at 2285,1735 h50 r90
BottomLayer:
  text "4" at 2175,1860 h50 r90
  text "B" at 2285,1860 h50 r90
GND (plane layer: these items are gaps in the copper):
  rectangle: 2050,1650 2350,2050
  region: 2075,1525 2075,1650 2050,1650 2050,1525
  region: 2350,1525 2350,1650 2325,1650 2325,1525
  region: 2350,1255 2350,1525 2050,1525 2050,1255
  lines w4: 2075,1275 2075,1400 ; 2075,1525 2195,1525 ; 2075,1650 2200,1650 2325,1650 ; 2075,1775 2200,1775 2325,1775 ; 2195,1400 2200,1400 ; 2200,1275 2200,1400 ; 2200,1525 2325,1525 ; 2325,1275 2325,1400 ; 2075,1400 2200,1400 ; 2075,1400 2075,1900 2200,1900 ; 2200,1400 2200,1900 ; 2200,1400 2325,1400 ; 2200,1900 2325,1900 2325,1400
  text "2" at 2175,1570 h50 r90
  text "B" at 2285,1570 h50 r90

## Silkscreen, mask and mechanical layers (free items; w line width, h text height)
TopOverlay:
  drawing of 5749 lines, arcs and shapes, not listed
  text "Motor control" at 2100,6445 h40
  text "IR" at -136,5926 h50
  text "USART2_CTS" at 1405,5925 h35 r90
  text "1" at 560,5920 h35
  text "2" at 700,5920 h35
  text "1" at 3270,5920 h35
  text "2" at 3400,5920 h35
  text "HDMI" at 3700,5890 h50 r90
  text "VBAT" at 1000,5840 h35
  text "3V3" at 1195,5840 h35
  text "GND" at 450,5825 h35
  text "PC6" at 785,5825 h35
  text "GND" at 3150,5825 h35
  text "PG8" at 3485,5825 h35
  text "MC_EnA" at 1725,5750 h35 r90
  text "MC_Stop" at 3080,5750 h35 r90
  text "PC7" at 450,5725 h35
  text "PC8" at 785,5725 h35
  text "PG7" at 3150,5725 h35
  text "PG6" at 3485,5725 h35
  text "MC_EnA" at 1405,5710 h35 r90
  text "PC9" at 455,5625 h35
  text "PA8" at 785,5625 h35
  text "PG5" at 3150,5625 h35
  text "PG4" at 3485,5625 h35
  text "MSD" at 215,5620 h50
  text "PG3" at 3150,5530 h35
  text "PA9" at 450,5525 h35
  text "PA10" at 785,5525 h35
  text "PG2" at 3485,5525 h35
  text "PA0" at 450,5450 h35
  text "GND" at 785,5425 h35
  text "PC13" at 3160,5425 h35
  text "GND" at 3485,5425 h35
  text "1" at 370,5405 h35
  text "MC_WH" at 950,5360 h40 r90
  text "PA11" at 785,5325 h35
  text "RST" at 3165,5325 h35
  text "PD13" at 3485,5325 h35
  text "PA12" at 445,5225 h35
  text "PA13" at 785,5225 h35
  text "PD12" at 3150,5225 h35
  text "PD11" at 3485,5225 h35
  text "PA14" at 445,5175 h35
  text "PA15" at 785,5125 h35
  text "PD10" at 3150,5125 h35
  text "PD9" at 3485,5125 h35
  text "1" at 2675,5120 h35
  text "HDMI" at 3710,5090 h50 r90
  text "PC10" at 445,5025 h35
  text "PC11" at 785,5025 h35
  text "USART1_RX" at 945,5025 h40 r90
  text "PD8" at 3150,5025 h35
  text "PB15" at 3485,5025 h35
  text "I2C1" at 2529,4952 h40 r90
  text "GND" at 450,4925 h35
  text "PC12" at 785,4925 h35
  text "D5V" at 3150,4925 h35
  text "PB14" at 3485,4925 h35
  text "PD0" at 475,4825 h35
  text "PD1" at 785,4825 h35
  text "PB13" at 3150,4825 h35
  text "PB12" at 3485,4825 h35
  text "NL" at 2525,4800 h40 r90
  text "PE2" at 475,4725 h35
  text "PE1" at 785,4725 h35
  text "PB11" at 3150,4725 h35
  text "PB10" at 3485,4725 h35
  text "MCO" at 2220,4690 h40
  text "PD2" at 475,4625 h35
  text "PD3" at 785,4625 h35
  text "PE15" at 3150,4625 h35
  text "PE14" at 3485,4625 h35
  text "PD4" at 475,4525 h35
  text "PD5" at 785,4525 h35
  text "PE13" at 3150,4525 h35
  text "PE12" at 3485,4525 h35
  text "PD6" at 475,4425 h35
  text "GND" at 785,4425 h35
  text "GND" at 3485,4425 h35
  text "PE11" at 3150,4420 h35
  text "BNC" at 3905,4420 h50
  text "PD7" at 480,4325 h35
  text "PG9" at 785,4325 h35
  text "PD15" at 3150,4325 h35
  text "PD14" at 3490,4325 h35
  text "PG10" at 445,4225 h35
  text "PG11" at 785,4225 h35
  text "PE9" at 3150,4225 h35
  text "PE10" at 3485,4225 h35
  text "BootL" at 1230,4200 h40 r90
  text "USART5" at 1402,4200 h40 r90
  text "BootL" at 1057,4199 h40 r90
  text "PG12" at 445,4125 h35
  text "PG13" at 785,4125 h35
  text "PE7" at 3150,4125 h35
  text "PE8" at 3485,4125 h35
  text "PG14" at 445,4025 h35
  text "PG15" at 785,4025 h35
  text "PG1" at 3150,4025 h35
  text "GND" at 445,3925 h35
  text "PB3" at 785,3925 h35
  text "GND" at 3150,3925 h35
  text "PG0" at 3485,3925 h35
  text "AIN+" at 2835,3855 h40
  text "AIN-" at 3005,3855 h40
  text "PB4" at 445,3825 h35
  text "PB5" at 785,3825 h35
  text "PF14" at 3150,3825 h35
  text "PF15" at 3485,3825 h35
  text "JTAG" at 4040,3770 h50
  text "PB6" at 445,3725 h35
  text "PB7" at 785,3725 h35
  text "PF12" at 3150,3725 h35
  text "PF13" at 3485,3725 h35
  text "USART2/RS232" at 360,3630 h50 r90
  text "PB8" at 445,3625 h35
  text "PB9" at 785,3625 h35
  text "PB2" at 3150,3625 h35
  text "PF11" at 3485,3625 h35
  text "Pin1" at 1265,3575 h30
  text "PE0" at 445,3525 h35
  text "3V3" at 790,3525 h35
  text "PB1" at 3150,3525 h35
  text "1" at 3865,3520 h35
  text "D5V" at 450,3425 h35
  text "GND" at 785,3425 h35
  text "GND" at 3485,3425 h35
  text "1" at 2750,3370 h40 r90
  text "PE4" at 445,3325 h35
  text "PE3" at 785,3325 h35
  text "PB0" at 3150,3325 h35
  text "PC5" at 3490,3325 h35
  text "VREF" at 2160,3255 h35
  text "PE6" at 445,3225 h35
  text "PE5" at 785,3225 h35
  text "PC4" at 3150,3225 h35
  text "PA7" at 3485,3225 h35
  text "0" at 2750,3170 h40 r90
  text "PC14" at 445,3125 h35
  text "PC13" at 785,3125 h35
  text "PA6" at 3150,3125 h35
  text "PA5" at 3485,3125 h35
  text "MCU_3V3" at 1250,3040 h35
  text "PF0" at 445,3025 h35
  text "PC15" at 785,3025 h35
  text "PA4" at 3150,3025 h35
  text "PA3" at 3485,3025 h35
  text "1" at 2450,2940 h40
  text "0" at 2565,2940 h40
  text "BOOT" at 2725,2940 h40
  text "GND" at 445,2925 h35
  text "PF1" at 785,2925 h35
  text "GND" at 3150,2925 h35
  text "PA2" at 3485,2925 h35
  text "Temp_INT" at 2100,2895 h35
  text "X" at 2450,2860 h40
  text "0" at 2565,2860 h40
  text "User  Flash" at 2660,2860 h40
  text "STlk: ST-LINK/V2 power source" at 950,2830 h36
  text "PF2" at 445,2825 h35
  text "PF3" at 785,2825 h35
  text "PA1" at 3155,2825 h35
  text "0" at 2450,2790 h40
  text "1" at 2570,2790 h40
  text "System memory" at 2660,2790 h40
  text "DTB: Daughter Board power source" at 950,2780 h36
  text "PF4" at 445,2725 h35
  text "PF5" at 785,2725 h35
  text "PSU: Power Supply Unit" at 950,2725 h36
  text "PC3" at 3155,2725 h35
  text "PC2" at 3485,2725 h35
  text "1" at 2455,2720 h40
  text "1" at 2570,2720 h40
  text "SRAM" at 2660,2720 h40
  text "MSB" at 1800,2675 h40
  text "LSB" at 2175,2675 h40
  text "5V" at 1595,2650 h35
  text "PF6" at 445,2625 h35
  text "PF7" at 785,2625 h35
  text "PC1" at 3155,2625 h35
  text "PC0" at 3485,2625 h35
  text "PSU" at 1275,2615 h35 r90
  text "STlk" at 1075,2610 h35 r90
  text "DTB" at 1175,2610 h35 r90
  text "PF8" at 440,2525 h35
  text "PF9" at 785,2525 h35
  text "PF10" at 3155,2525 h35
  text "3V3" at 445,2425 h35
  text "GND" at 785,2425 h35
  text "MC_PFC" at 3125,2425 h35 r90
  text "3V3" at 3155,2425 h35
  text "GND" at 3485,2425 h35
  text "Audio" at 1374.65,2400.35 h35 r90
  text "E2P_WP" at 1665,2400 h40 r90
  text "69" at 600,2345 h35
  text "70" at 700,2345 h35
  text "69" at 3300,2345 h35
  text "70" at 3400,2345 h35
  text "PF9 . . PF6" at 1860,2325 h40
  text "USART1/RS232 & USART5/RS485" at 360,2320 h50 r90
  text "3V3" at 1530,2315 h35
  text "Audio JACK" at -160,1705 h50
  text "ST-LINK/V2" at 3810,1700 h50
  text "5V" at -187,1576 h40
  text "COM" at 3970,1360 h40
  text "B" at 2285,1325 h50 r90
  text "S" at 2175,1320 h50 r90
  text "1" at 2340,1235 h35
  text "PSU" at -175,975 h50
  text "DC5V" at 0,975 h50
  text "IrDA" at 4060,705 h50
  text "ADC" at 4020,525 h50
  text "-" at -30,435 h40 r90
  text "+" at 150,430 h40 r90
  text "GND" at 230,-125 h35
BottomOverlay:
  drawing of 2332 lines, arcs and shapes, not listed
  text "B" at 2175,1975 h50 r90
  text "B" at 2285,1975 h50 r90
Mechanical1:
  lines w5: -225,-425 -225,5025 ccw(c-1380.29,5270.56) -225,5516.13 -225,6575 4275,6575 4275,-425 -225,-425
